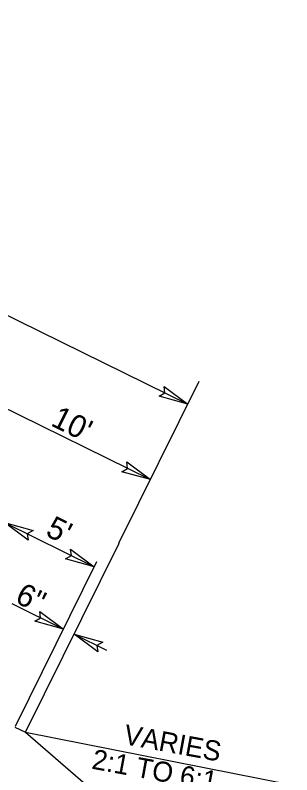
# Model space of a CAD drawing. Extents: x 1518247 to 1523638, y 635234 to 639927.
# Drawn here: x 1520984.1 to 1521122, y 635922.9 to 636302.2 of the extents above; entities that cross this region are included whole.
import ezdxf

# ---------------------------------------------------------------- set-up
doc = ezdxf.new("R2010")
doc.units = 0
for name, color, linetype in [('Prop Dimension', 7, 'Continuous'), ('Prop Shade Light', 7, 'Continuous'), ('Typical Berm CELL', 7, 'Continuous'), ('Typical Hinge Slope Arterial CELL', 7, 'Continuous'), ('Typical Hinge Slope Interstate CELL', 7, 'Continuous')]:
    doc.layers.add(name, color=color, linetype=linetype)

# ---------------------------------------------------------------- blocks, each defined once
blk = doc.blocks.new('TERMINATOR')
at = {"layer": 'Prop Shade Light'}
blk.add_lwpolyline([(-0.469, 0.081), (0, 0), (-0.471, -0.083), (-0.411, 0)], close=True, dxfattribs=at)

msp = doc.modelspace()

# ---------------------------------------------------------------- linework, layer by layer
at = {"layer": 'Prop Dimension'}
for p, q in [((1520181.21, 636547.04), (1521070.13, 636107.93)), ((1521035.85, 636038.55), (1521075.86, 636119.54)), ((1520964.04, 636113.52), (1521051.53, 636070.3)), ((1520978.71, 636048.89), (1521023.54, 636026.74)), ((1520989.47, 635944.61), (1521035.88, 636038.54)), ((1520984.24, 635947.19), (1521024.86, 636029.41)), ((1520982.4, 636008.43), (1521008.2, 635995.69)), ((1521013.43, 635993.1), (1521029.64, 635985.1))]:
    msp.add_line(p, q, dxfattribs=at)
at = {"layer": 'Typical Berm CELL'}
msp.add_line((1520984, 635946.7), (1520989.29, 635944.24), dxfattribs=at)
at = {"layer": 'Typical Hinge Slope Interstate CELL'}
for q in [(1521091.56, 635855.66), (1521122, 635917.9)]:
    msp.add_line((1520989.29, 635944.24), q, dxfattribs=at)

# ---------------------------------------------------------------- block references
at = {"layer": 'Prop Dimension', "xscale": 30.9388560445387, "yscale": 33.305184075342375}
for p, rotation in [((1521070.13, 636107.93), -26.28853950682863), ((1521051.53, 636070.3), -26.28853950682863), ((1520978.71, 636048.89), 153.71146049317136), ((1521023.54, 636026.74), -26.28853950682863), ((1521008.2, 635995.69), -26.28853950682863), ((1521013.43, 635993.1), 153.71146049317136)]:
    msp.add_blockref('TERMINATOR', p, dxfattribs=dict(at, rotation=rotation))

# ---------------------------------------------------------------- texts
at = {"layer": 'Prop Dimension'}
for s, p in [("10'", (1521001.35, 636097.54)), ("5'", (1520998.68, 636042.59)), ('6"', (1520983.46, 636009.25))]:
    msp.add_text(s, height=11.189, rotation=333.7115, dxfattribs=at).set_placement(p)
at = {"layer": 'Typical Hinge Slope Arterial CELL'}
for s, p in [('VARIES', (1521037.67, 635938.33)), ('2:1 TO 6:1', (1521021.82, 635926.04))]:
    msp.add_text(s, height=9.969, rotation=349.5717, dxfattribs=at).set_placement(p)

doc.saveas('drawing.dxf')
